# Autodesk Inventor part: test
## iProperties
Shininess: 70.0
Length Units: 11269
Angle Units: 11279
Time Units: 11290
Mass Units: 11283
Length Display Precision: 3
Angle Display Precision: 2
Part Number: test
Material: 1.4301
Document SubType Name: Modeling
Vendor: DIN Norm
Designer: M.Ettwein
Project: Abmessung
Created: 2004-05
Manufacturer: Standard
Standards Organization: Custom
Density: 0.0
Volumn: 0.0
Area: 0.0
PropertySet Name: Model Information
Control State: 0
Master: False
Checked Out: False
Revision Number: Zeichnungsnr.
Author: M.Ettwein
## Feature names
1. Extrusion2
